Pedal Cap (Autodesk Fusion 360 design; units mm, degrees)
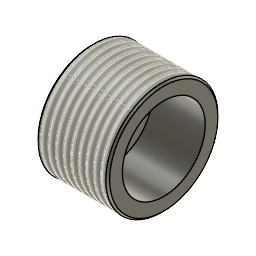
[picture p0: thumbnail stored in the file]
part number: 2025-12-16-11-19-28-387
sketch "Sketch1" plane through (0, 0, 0) normal (0, 0, 1) x axis (1, 0, 0)
  line L1 (7, 0) -> (0, 0)
  line L2 (0, 5.5) -> (0, 0)
  line L3 (7, 5.5) -> (0, 5.5)
  line L4 (7, 7.5) -> (7, 5.5)
  line L5 (-2.5, 7.5) -> (7, 7.5)
  line L6 (-2.5, 0) -> (-2.5, 7.5)
  line L7 (0, 0) -> (-2.5, 0)
  point P1 (0, 0)
  point P2 (0, 0)
  point P4 (0, 0)
  point P10 (0, 0)
  point P3 (7, 0)
  point P9 (-2.5, 0)
  point P5 (0, 5.5)
  point P6 (7, 5.5)
  coincident P1 P2
  horizontal L1
  coincident P1 P4
  perpendicular L1 L2
  perpendicular L2 L3
  perpendicular L3 L4
  perpendicular L4 L5
  perpendicular L1 L6
  coincident P1 P10
  perpendicular L2 L7
  coincident P3 L4
  dimension "d1" distance P2 P3 = 7
  dimension "d2" = 11
  dimension "d3" = 15
  dimension "d4" distance P9 P10 = 2.5
  dimension "d5" distance P5 P6 = 7
revolve "Revolve1" sketch "Sketch1" AlongAngle 360
sketch "Sketch2" plane through (-2.5, 0, 0) normal (-1, 0, 0) x axis (0, -1, 0)
  line L1 (-3.4641, 0) -> (-1.7321, 3)
  line L2 (-1.7321, -3) -> (-3.4641, 0)
  line L3 (1.7321, -3) -> (-1.7321, -3)
  line L4 (3.4641, 0) -> (1.7321, -3)
  line L5 (1.7321, 3) -> (3.4641, 0)
  line L6 (-1.7321, 3) -> (1.7321, 3)
  circle C1 centre (0, 0) radius 7.5
  point P1 (0, 0)
  point P9 (0, 0)
  coincident P1 P9
  horizontal L6
  dimension "d7" distance L3 L6 = 6
extrude "Extrude1" cut sketch "Sketch2" profile of L1 L2 L3 L4 L5 L6 against normal blind 2
thread "Thread1" ThreadOffset 0 ThreadLength 10
chamfer "Chamfer1" distance 0.25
